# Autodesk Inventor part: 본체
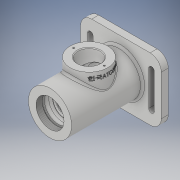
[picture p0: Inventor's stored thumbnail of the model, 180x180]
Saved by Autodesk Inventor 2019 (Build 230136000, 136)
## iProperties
Created: 2021-07
Part Number: 본체
Material: 일반
Document SubType Name: Modeling
Designer: jun-2-7
Mass: 276.662 g
Surface Area: 646.09 cm^2
Volume: 276.662 cm^3
Density: 1 g/cm^3
Appearance: 기본값
Author: jun-2-7
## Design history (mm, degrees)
sketch "스케치1"
  geometry: L1 (0, 51)-(31, 51); L2 (31, 51)-(31, -51); L3 (31, -51)-(0, -51); L4 (-6.2, 0)-(37.2, 0) reference; L5 (0, -71.4)-(0, 71.4) reference; L6 (0, 51)-(0, -51); L7 (0, 51)-(0, -51); 1 further point
  constraints: 10 end point, 2 collinear, 2 perpendicular, 2 point on line, 1 horizontal, 1 other
  dimensions: "d0" = 102 distance of L1.end L2.end; "d1" = 62 diameter of L2 L5
revolve "회전1" sketch "스케치1" stored, may be unused: angle "d2" = 90 deg
sketch "스케치2"
  geometry: L1 (58, -45)-(-58, -45); L2 (-58, -45)-(-58, 45); L3 (-58, 45)-(58, 45); L4 (58, 45)-(58, -45); L5 (58, -45)-(-58, 45); L6 (-58, -45)-(58, 45); 1 further point
  constraints: 12 end point, 2 midpoint, 2 parallel, 1 horizontal, 1 perpendicular
  dimensions: "d3" = 116 distance of L2.end L3.end; "d4" = 90 distance of L3.end L1.start
extrude "돌출1" join sketch "스케치2" distance "d5" = 10; taper "d6" = 0 deg
node "작업 평면2"
sketch "스케치4"
  geometry: L1 (-31, 51)-(31, 51) reference; C1 r 27 at (0, -5); 2 further points
  constraints: 1 centre point, 1 coincident, 1 midpoint, 1 vertical alignment
  dimensions: "d8" = 54 diameter of C1; "d65" = 56 distance from line of L1 point (0, -5)
extrude "돌출2" join sketch "스케치4" stored distance "d9" = 3; taper "d10" = 0 deg
sketch "스케치5"
  geometry: C1 r 35 at (0, 0); 1 further point
  constraints: 1 centre point, 1 coincident
  dimensions: "d11" = 70 diameter of C1
extrude "돌출3" join sketch "스케치5" distance "d12" = 3; taper "d13" = 0 deg
sketch "스케치9"
  geometry: 2 further points
  constraints: 1 coincident
hole "구멍2" sketch "스케치9" at (0, 0) diameter "d21" = 40.376; stored, may be unused: countersink angle "d25" = 90 deg, drill point angle "d27" = 0 deg; dims "d22" = 9, "d23" = 4, "d24" = 2, "d26" = 9
sketch "스케치11"
  geometry: C1 r 24 at (0, 0); 1 further point
  constraints: 1 centre point, 1 coincident
  dimensions: "d32" = 48 diameter of C1
extrude "돌출4" cut sketch "스케치11" distance "d33" = 3; taper "d34" = 0 deg
sketch "스케치12"
  geometry: C1 r 20 at (0, 0); 1 further point
  constraints: 1 centre point, 1 coincident
  dimensions: "d35" = 40 diameter of C1
extrude "돌출5" cut sketch "스케치12" distance "d36" = 9; taper "d37" = 0 deg
fillet "모깎기1" dims "d39" = 3
revolve "회전2" stored, may be unused: angle "d89" = 90 deg
fillet "모깎기3" dims "d90" = 16
sketch "스케치21"
  geometry: L1 (42, -45)-(-42, -45) reference; L2 (-58, -29)-(-58, 29) reference; L3 (-42, 45)-(42, 45) reference; L4 (58, 29)-(58, -29) reference; L5 (85.839, 0)-(-85.839, 0) reference; L6 (0, -67.639)-(0, 67.639) reference; L7 (-44, 25)-(-44, -25); L8 (-40, 25)-(-40, -25); L9 (-48, -25)-(-48, 25); L10 (-42, 29)-(-42, -29); L11 (40, 25)-(40, -25); L12 (44, 25)-(44, -25); L13 (48, -25)-(48, 25); L14 (42, 29)-(42, -29); C1 r 31 at (0, 0) reference; A1 r 16 centre (42, -29) between (42, -45) and (58, -29) reference; A2 r 16 centre (-42, -29) between (-58, -29) and (-42, -45) reference; A3 r 16 centre (-42, 29) between (-42, 45) and (-58, 29) reference; A4 r 16 centre (42, 29) between (58, 29) and (42, 45) reference; A5 r 4 centre (-44, 25) between (-40, 25) and (-48, 25); A6 r 4 centre (-44, -25) between (-48, -25) and (-40, -25); A7 r 4 centre (44, 25) between (48, 25) and (40, 25); A8 r 4 centre (44, -25) between (40, -25) and (48, -25); 3 further points
  constraints: 20 end point, 9 symmetric about line, 8 point on circle, 4 centre point, 4 tangent, 2 vertical, 1 midpoint, 1 parallel, 1 point on line, 2 other
  dimensions: "d91" = 4 radius of A5; "d92" = 44 distance of point (0, 0) point (-44, 0); "d93" = 50 distance of L7.start L7.end
extrude "돌출10" cut sketch "스케치21" extent not by distance; stored distance "d94" = 0; taper "d95" = 0 deg
sketch "스케치22"
  geometry: C1 r 27 at (0, 0) reference; C2 r 16 at (0, 0); 1 further point
  constraints: 1 centre point, 1 coincident
  dimensions: "d96" = 32 diameter of C2
extrude "돌출11" cut sketch "스케치22" stored distance "d97" = 38; taper "d98" = 0 deg
sketch "스케치23"
  geometry: L1 (-81.2, -5)-(81.2, -5) reference; L2 (0, 82)-(0, -79) reference; C1 r 16 at (0, 0) reference; C2 r 27 at (0, 0) reference; A1 r 22 centre (0, 0) between (22, 0) and (-22, 0); 1 further point
  constraints: 2 point on circle, 1 centre point, 1 coincident
  dimensions: "d99" = 44 diameter of A1
hole "구멍3" sketch "스케치23" at (22, 0), (-22, 0) diameter "d100" = 2.459; stored, may be unused: countersink angle "d104" = 90 deg, drill point angle "d106" = 118 deg; dims "d101" = 6, "d102" = 4, "d103" = 2, "d105" = 8
node "작업 평면3"
sketch "스케치24"
  geometry: L1 (-105, 5)-(21, 5) reference; L2 (-42, -82)-(-42, 79) reference; L3 (0, 27)-(0, -27) reference; L4 (17.704, 0)-(-49.483, 0); L5 (0, 27)-(-11, 27) reference; 2 further points
  constraints: 2 end point, 1 horizontal, 1 other
  dimensions: "d107" = 27 distance from line of L3.end L4; "d108" = 27 distance from line of point (-8, 0) L5; "d109" = 8 distance from line of point (-8, 0) L3
feature "엠보싱1" sketch "스케치24" dims "d0" = 102, "d1" = 62, "d110" = 0.5, "d111" = 0
fillet "모깎기4" dims "d112" = 3
fillet "모깎기5" dims "d113" = 3
chamfer "모따기3" distance "d114" = 1; stored, may be unused: second distance "d115" = 2, angle "d116" = 45 deg
fillet "모깎기6" dims "d121" = 3
chamfer "모따기4" distance "d122" = 0.7; stored, may be unused: second distance "d123" = 2, angle "d124" = 30 deg
node "솔리드1"
sketch "스케치20"
  geometry: L1 (-20.188, 51)-(20.188, 51) reference; L2 (20.188, 42)-(-20.188, 42) reference; L3 (-17, 30)-(17, 30) reference; L4 (20, 33)-(-20, 33) reference; L5 (0, 74)-(0, -87) reference; L6 (-63, 0)-(63, 0) reference; L7 (0, -87)-(0, 74) reference; L8 (-17, 30)-(17, 30) reference; L9 (0, 30)-(17.5, 30); L10 (17.5, 30)-(17.5, 26.75); L11 (17.5, 26.75)-(18.5, 26.75); L12 (18.5, 26.75)-(18.5, 25); L13 (18.5, 25)-(17.5, 25); L14 (17.5, 25)-(17.5, 15); L15 (18.5, 14)-(23, 14); L16 (26, 11)-(26, -21); L17 (-31, 51)-(31, 51) reference; L18 (23, -24)-(18.5, -24); L19 (17.5, -25)-(17.5, -34.7); L20 (17.2, -35)-(16, -35); L21 (16, -35)-(16, -37); L22 (13, -40)-(10, -40); L23 (10, -40)-(10, -46.693); L24 (10, -46.693)-(12.2, -46.693); L25 (12.5, -46.993)-(12.5, -49.3); L26 (16, -53.993)-(22, -64); L27 (-35, -64)-(35, -64) reference; L28 (17.5, 15)-(18.5, 14); L29 (18.5, -24)-(17.5, -25); L30 (0, 30)-(0, -64); L31 (0, -64)-(22, -64); L32 (16, -53.993)-(12.5, -53.993); L33 (12.5, -53.993)-(12.5, -49.3); A1 r 0.3 centre (12.2, -46.993) between (12.5, -46.993) and (12.2, -46.693); A2 r 3 centre (23, 11) between (26, 11) and (23, 14); A3 r 3 centre (23, -21) between (23, -24) and (26, -21); A4 r 0.3 centre (17.2, -34.7) between (17.2, -35) and (17.5, -34.7); A5 r 3 centre (13, -37) between (13, -40) and (16, -37); 7 further points
  constraints: 46 end point, 14 point on line, 13 perpendicular, 10 point on circle, 10 tangent, 5 centre point, 3 midpoint, 2 horizontal, 1 collinear, 1 equal radius, 1 vertical
  dimensions: "d59" = 35 diameter of L10 L5; "d60" = 1.75 distance of L11.end L12.end; "d61" = 37 diameter of L12 L5; "d62" = 11 distance of L13.end point (17.5, 14); "d64" = 56 distance from line of point (26, -5) L17; "d66" = 38 distance of point (26, 14) point (26, -24); "d67" = 52 diameter of L16 L5; "d68" = 35 diameter of L19 L5; "d69" = 32 diameter of L21 L5; "d70" = 20 diameter of L23 L5; "d71" = 25 diameter of L25 L5; "d72" = 44 diameter of L26.end L5; "d73" = 11 distance of point (17.5, -24) point (17.5, -35); "d75" = 24 distance from line of L27 L22.end; "d78" = 0.3 radius of A1; "d82" = 1 distance of L14.end point (17.5, 14); "d83" = 1 distance of L15.start point (17.5, 14) (= d82); "d84" = 3 radius of A2 (derived); "d85" = 1 distance of L18.end point (17.5, -24); "d86" = 1 distance of L19.start point (17.5, -24) (= d85); "d87" = 0.3 radius of A4; "d88" = 3 radius of A5; "d118" = 10.00731 vertical distance of L32.end L26.end; "d119" = 16 distance from line of L30 L26.start; "d120" = 7.3 distance between parallel lines of L32 L24
node "투영된 루프5"
node "투영된 루프6"
node "투영된 루프7"
node "투영된 루프8"
node "투영된 루프9"
other parameters: "d7" = 42
